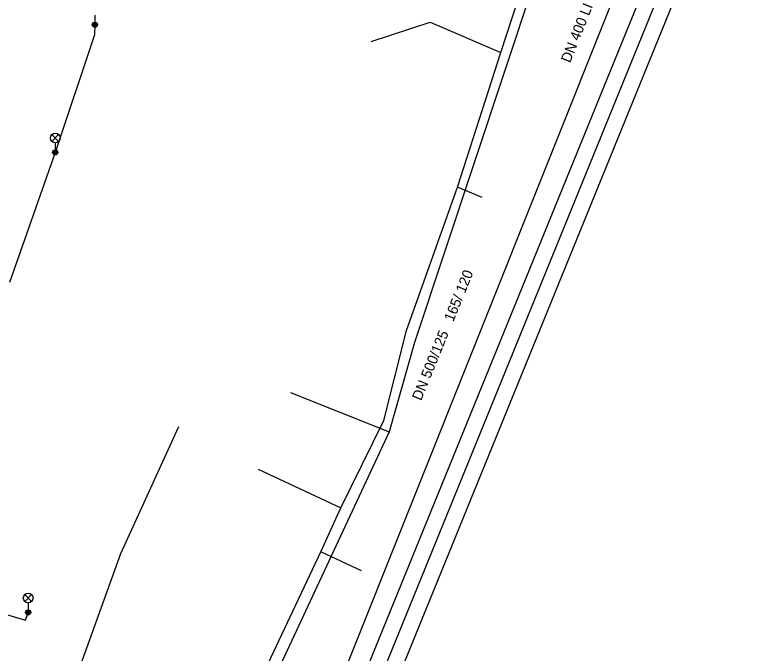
# Model space of a CAD drawing. Extents: x -596024 to -594475, y -1163820 to -1161957.
# Drawn here: x -594674.7 to -594616.3, y -1162184.4 to -1162134.9 of the extents above; entities that cross this region are included whole.
import ezdxf

# ---------------------------------------------------------------- set-up
doc = ezdxf.new("R2010")
doc.units = 0
for name, color, linetype in [('Vrstva 1', 7, 'Continuous'), ('Vrstva 12', 7, 'Continuous'), ('Vrstva 13', 7, 'Continuous'), ('Vrstva 15', 7, 'Continuous'), ('Vrstva 29', 7, 'Continuous'), ('Vrstva 30', 7, 'Continuous'), ('Vrstva 32', 7, 'Continuous'), ('Vrstva 5', 7, 'Continuous'), ('Vrstva 55', 7, 'Continuous'), ('Vrstva 56', 7, 'Continuous'), ('Vrstva 9', 7, 'Continuous')]:
    doc.layers.add(name, color=color, linetype=linetype)

msp = doc.modelspace()

# ---------------------------------------------------------------- linework, layer by layer
at = {"layer": 'Vrstva 1'}
for p, q in [((-594637.099, -1162137.801), (-594633.205, -1162125.939)), ((-594638.532, -1162149.036), (-594640.457, -1162148.23)), ((-594655.899, -1162170.074), (-594649.497, -1162173.076)), ((-594647.881, -1162177.953), (-594651.045, -1162176.482))]:
    msp.add_line(p, q, dxfattribs=at)
for points in [[(-594635.801, -1162122.497), (-594633.396, -1162123.481), (-594632.194, -1162125.339), (-594643.776, -1162160.263)], [(-594647.126, -1162136.95), (-594642.56, -1162135.473), (-594637.099, -1162137.801)], [(-594644.396, -1162159.331), (-594640.457, -1162148.23), (-594637.099, -1162137.801)], [(-594657.712, -1162190.613), (-594651.045, -1162176.482), (-594649.497, -1162173.076), (-594646.15, -1162166.316), (-594644.396, -1162159.331)]]:
    msp.add_lwpolyline(points, dxfattribs=at)
at = {"layer": 'Vrstva 12'}
msp.add_lwpolyline([(-594680.74, -1162219.01), (-594681.49, -1162217.26), (-594679.84, -1162209.75), (-594678.37, -1162207.25), (-594676.2, -1162201.98), (-594672.39, -1162191.66), (-594669.77, -1162185.57), (-594666.54, -1162176.61), (-594662.03, -1162166.78)], dxfattribs=at)
at = {"layer": 'Vrstva 13'}
msp.add_line((-594596.819, -1162054.54), (-594654.099, -1162197.927), dxfattribs=at)
at = {"layer": 'Vrstva 29'}
msp.add_lwpolyline([(-594527.721, -1162116.547), (-594550.035, -1162144.733), (-594618.49, -1162117.698), (-594660.636, -1162221.142), (-594706.437, -1162202.481)], dxfattribs=at)
at = {"layer": 'Vrstva 30'}
for points in [[(-594706.74, -1162201.008), (-594661.322, -1162219.513), (-594619.181, -1162116.081), (-594550.439, -1162143.229), (-594528.701, -1162115.771)], [(-594526.741, -1162117.323), (-594549.631, -1162146.237), (-594617.799, -1162119.315), (-594659.95, -1162222.771), (-594706.133, -1162203.955)]]:
    msp.add_lwpolyline(points, dxfattribs=at)
at = {"layer": 'Vrstva 5'}
msp.add_line((-594653.395, -1162164.134), (-594645.745, -1162167.194), dxfattribs=at)
at = {"layer": 'Vrstva 55'}
for p, q in [((-594668.542, -1162135.663), (-594668.572, -1162136.454)), ((-594668.572, -1162136.454), (-594671.614, -1162145.553)), ((-594671.614, -1162145.553), (-594675.163, -1162155.628)), ((-594687.52, -1162177.716), (-594673.927, -1162181.774)), ((-594673.927, -1162181.774), (-594673.71, -1162181.179))]:
    msp.add_line(p, q, dxfattribs=at)
at = {"layer": 'Vrstva 56'}
for p, q in [((-594668.542, -1162134.913), (-594668.542, -1162135.663)), ((-594671.879, -1162144.693), (-594671.349, -1162144.163)), ((-594671.879, -1162144.163), (-594671.349, -1162144.693)), ((-594671.614, -1162144.803), (-594671.614, -1162145.553)), ((-594673.975, -1162180.319), (-594673.445, -1162179.789)), ((-594673.975, -1162179.789), (-594673.445, -1162180.319)), ((-594673.71, -1162180.429), (-594673.71, -1162181.179))]:
    msp.add_line(p, q, dxfattribs=at)
for centre, radius in [((-594668.542, -1162135.663), 0.2), ((-594668.542, -1162135.663), 0.145), ((-594668.542, -1162135.663), 0.0876), ((-594671.614, -1162144.428), 0.375), ((-594671.614, -1162145.553), 0.2), ((-594671.614, -1162145.553), 0.145), ((-594671.614, -1162145.553), 0.0876), ((-594673.71, -1162180.054), 0.375), ((-594673.71, -1162181.179), 0.2), ((-594673.71, -1162181.179), 0.145), ((-594673.71, -1162181.179), 0.0876)]:
    msp.add_circle(centre, radius, dxfattribs=at)
at = {"layer": 'Vrstva 9'}
msp.add_lwpolyline([(-594643.776, -1162160.263), (-594645.745, -1162167.194), (-594667.318, -1162213.397)], dxfattribs=at)

# ---------------------------------------------------------------- texts
at = {"layer": 'Vrstva 15'}
msp.add_text('DN 400 LI', height=0.8, rotation=68.29657, dxfattribs=at).set_placement((-594631.725, -1162138.666))
at = {"layer": 'Vrstva 32'}
msp.add_text('DN 500/125   165/ 120', height=0.8, rotation=67.8382, dxfattribs=at).set_placement((-594643.269, -1162164.827))

doc.saveas('drawing.dxf')
